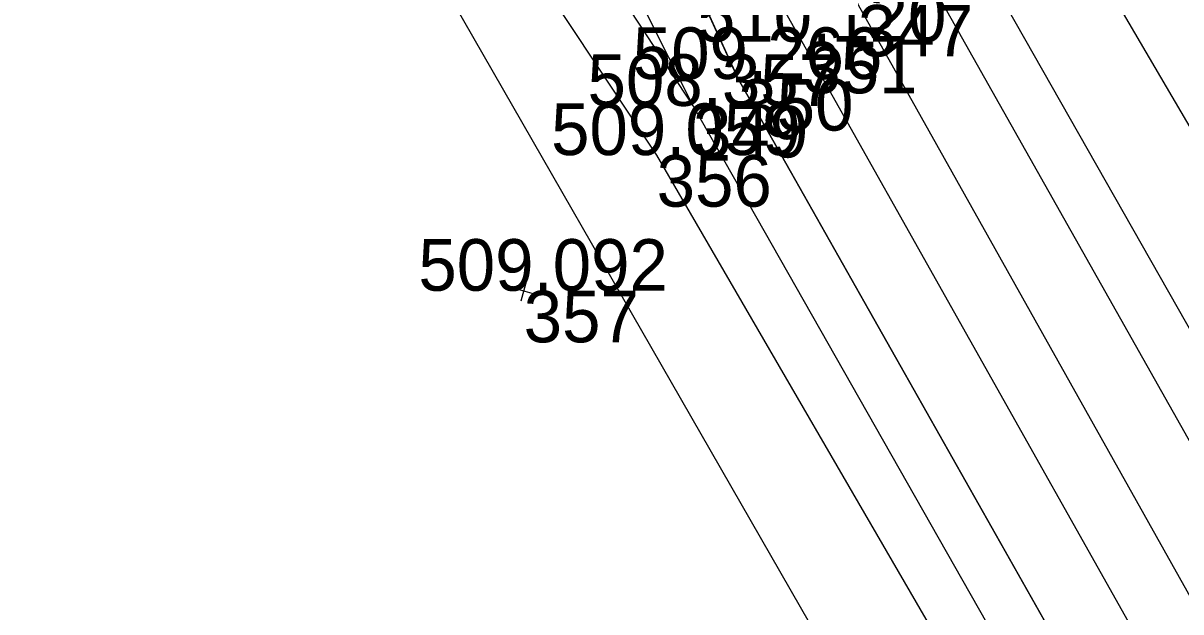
# Model space of a CAD drawing. Extents: x -1234191 to 23050, y -1290331 to -741191.
# Drawn here: x -865331.07 to -865304.16, y -1105803.44 to -1105789.74 of the extents above; entities that cross this region are included whole.
import ezdxf

# ---------------------------------------------------------------- set-up
doc = ezdxf.new("R2010")
doc.units = 0
for name, color, linetype in [('Vrstva 1', 7, 'Continuous'), ('Vrstva 4', 7, 'Continuous'), ('Vrstva 49', 7, 'Continuous'), ('Vrstva 53', 7, 'Continuous'), ('Vrstva 60', 7, 'Continuous'), ('Vrstva 61', 7, 'Continuous')]:
    doc.layers.add(name, color=color, linetype=linetype)

msp = doc.modelspace()

# ---------------------------------------------------------------- linework, layer by layer
at = {"layer": 'Vrstva 1'}
msp.add_lwpolyline([(-865407.195, -1105537.575), (-865404.196, -1105556.916), (-865400.505, -1105576.045), (-865396.019, -1105595.579), (-865390.864, -1105614.993), (-865387.31, -1105627.062), (-865386.583, -1105629.41), (-865385.508, -1105632.843), (-865385.189, -1105633.841), (-865378.995, -1105652.192), (-865371.92, -1105670.917), (-865371.888, -1105670.985), (-865364.336, -1105688.963), (-865356.164, -1105706.667), (-865347.54, -1105724.058), (-865338.705, -1105740.819), (-865331.549, -1105753.838), (-865329.651, -1105757.233), (-865318.339, -1105777.438), (-865311.668, -1105789.318), (-865293.803, -1105821.189)], dxfattribs=at)
at = {"layer": 'Vrstva 4'}
for points in [[(-865415.794, -1105407.513), (-865415.013, -1105426.565), (-865414.095, -1105450.467), (-865411.461, -1105474.692), (-865410.067, -1105496.27), (-865407.861, -1105518.057), (-865405.51, -1105537.281), (-865402.299, -1105556.567), (-865398.435, -1105575.517), (-865393.919, -1105595.097), (-865389.455, -1105614.694), (-865383.953, -1105633.214), (-865377.686, -1105651.781), (-865370.49, -1105670.425), (-865362.745, -1105688.31), (-865354.733, -1105705.921), (-865346.085, -1105723.231), (-865337.304, -1105740.107), (-865328.117, -1105756.476), (-865310.177, -1105788.444), (-865292.191, -1105820.356)], [(-865241.394, -1105918.847), (-865246.199, -1105909.181), (-865270.794, -1105865.582), (-865295.111, -1105821.951), (-865312.962, -1105790.175), (-865331.022, -1105758.107), (-865339.935, -1105741.481), (-865348.821, -1105724.714), (-865357.635, -1105707.335), (-865365.696, -1105689.589), (-865373.312, -1105671.543), (-865380.292, -1105652.6), (-865386.741, -1105634.019), (-865392.22, -1105615.411), (-865397.526, -1105595.969), (-865401.976, -1105576.338), (-865405.628, -1105557.197), (-865408.672, -1105537.755), (-865411.141, -1105518.31), (-865413.538, -1105496.503), (-865416.279, -1105475.043), (-865418.369, -1105450.916), (-865420.427, -1105426.616), (-865421.339, -1105417.317)], [(-865296.635, -1105822.585), (-865314.451, -1105791.041), (-865319.551, -1105779.817), (-865319.292, -1105779.667), (-865319.976, -1105778.485), (-865320.819, -1105777.032), (-865321.078, -1105777.182), (-865332.077, -1105758.784), (-865341.611, -1105742.183), (-865350.523, -1105725.488), (-865354.5, -1105715.084), (-865358.525, -1105707.694), (-865366.664, -1105690.21), (-865373.988, -1105671.921), (-865381.072, -1105652.973), (-865387.566, -1105634.336), (-865393.24, -1105615.741), (-865398.46, -1105596.137), (-865402.659, -1105576.601), (-865406.297, -1105557.39), (-865409.325, -1105537.816), (-865412.231, -1105518.228), (-865414.324, -1105496.685), (-865416.279, -1105475.043)], [(-865290.412, -1105820.701), (-865309.044, -1105787.892), (-865315.278, -1105777.501), (-865315.71, -1105777.749), (-865317.243, -1105775.084), (-865316.811, -1105774.836), (-865326.688, -1105756.737), (-865327.874, -1105753.694), (-865328.151, -1105753.201), (-865328.953, -1105752.245), (-865329.085, -1105752.053), (-865330.489, -1105749.795), (-865330.581, -1105749.581), (-865335.947, -1105739.356), (-865344.587, -1105722.614), (-865344.541, -1105720.805), (-865348.241, -1105716.088), (-865347.945, -1105715.864), (-865349.677, -1105712.823), (-865349.47, -1105712.632), (-865353.649, -1105705.349), (-865362.099, -1105687.748), (-865369.612, -1105670.045)]]:
    msp.add_lwpolyline(points, dxfattribs=at)
at = {"layer": 'Vrstva 49'}
for p, q in [((-865319.371, -1105795.726), (-865319.507, -1105796.208)), ((-865319.68, -1105795.899), (-865319.198, -1105796.035))]:
    msp.add_line(p, q, dxfattribs=at)
for points in [[(-865238.139, -1105906.641), (-865245.971, -1105899.377), (-865264.35, -1105861.222), (-865287.233, -1105820.677), (-865307.045, -1105786.866), (-865311.706, -1105776.535), (-865313.122, -1105777.444), (-865315.278, -1105777.501), (-865315.411, -1105777.27)], [(-865315.503, -1105791.667), (-865321.127, -1105780.475), (-865320.839, -1105780.85), (-865319.732, -1105779.504)], [(-865319.732, -1105779.504), (-865319.551, -1105779.817), (-865314.451, -1105791.041), (-865296.635, -1105822.585), (-865271.761, -1105866.129), (-865247.643, -1105909.906), (-865246.453, -1105912.566), (-865245.509, -1105913.675), (-865244.664, -1105914.724)], [(-865242.981, -1105917.729), (-865243.463, -1105916.869), (-865244.406, -1105917.32), (-865246.254, -1105914.641), (-865246.071, -1105914.316), (-865245.908, -1105913.914), (-865247.936, -1105911.292), (-865273.042, -1105866.892), (-865297.608, -1105823.186), (-865315.503, -1105791.667), (-865322.602, -1105780.841), (-865326.658, -1105782.604)], [(-865327.665, -1105784.514), (-865323.155, -1105782.583), (-865316.348, -1105792.811), (-865298.436, -1105823.696), (-865274.126, -1105867.599), (-865249.338, -1105911.884), (-865245.595, -1105918.34), (-865243.068, -1105917.778), (-865242.981, -1105917.729)]]:
    msp.add_lwpolyline(points, dxfattribs=at)
at = {"layer": 'Vrstva 53'}
msp.add_lwpolyline([(-865241.975, -1105927.132), (-865328.685, -1105775.989), (-865337.293, -1105781.984), (-865359.64, -1105740.13), (-865378.04, -1105702.85), (-865401.73, -1105642.98)], dxfattribs=at)
at = {"layer": 'Vrstva 60'}
for p, q in [((-865312.962, -1105790.175), (-865312.962, -1105790.175)), ((-865314.451, -1105791.041), (-865314.451, -1105791.041)), ((-865315.503, -1105791.667), (-865315.503, -1105791.667)), ((-865316.348, -1105792.811), (-865316.348, -1105792.811)), ((-865319.439, -1105795.967), (-865319.439, -1105795.967))]:
    msp.add_line(p, q, dxfattribs=at)

# ---------------------------------------------------------------- texts
for s, p in [('347', (-865311.668, -1105790.518)), ('351', (-865312.962, -1105791.375)), ('350', (-865314.451, -1105792.241)), ('349', (-865315.503, -1105792.867)), ('356', (-865316.348, -1105794.011)), ('357', (-865319.439, -1105797.167))]:
    msp.add_text(s, height=1.2, dxfattribs=at).set_placement(p)
at = {"layer": 'Vrstva 61'}
for s, p in [('510.120', (-865315.413, -1105790.175)), ('509.266', (-865316.903, -1105791.041)), ('508.357', (-865317.955, -1105791.667)), ('509.059', (-865318.802, -1105792.811)), ('509.092', (-865321.887, -1105795.967))]:
    msp.add_text(s, height=1.2, dxfattribs=at).set_placement(p)

doc.saveas('drawing.dxf')
